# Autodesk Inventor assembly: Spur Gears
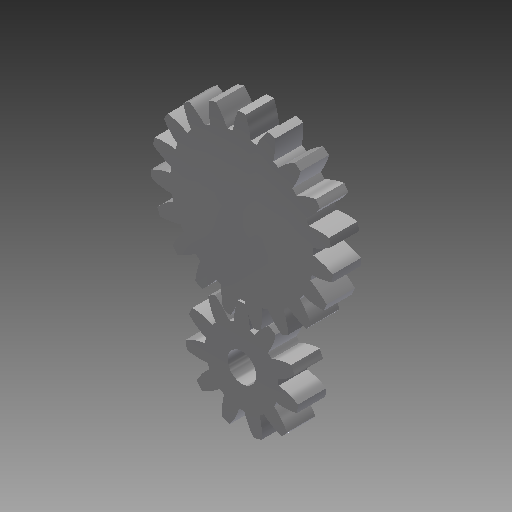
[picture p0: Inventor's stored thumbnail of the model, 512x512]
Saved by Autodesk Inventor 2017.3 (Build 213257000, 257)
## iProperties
ClientObjectVersion: 1
Created: 2020-03
Part Number: Spur Gears
Document SubType Name: Assembly
Designer: Tim_G
Categories: <?xml version="1.0" encoding="UTF-16"?> <MemberInstance><Categories><FamilyTemplate/><ParamToTemplateMap><ParamToTemplate><ParamToTemplate CategoryParameter="//
Author: Tim_G
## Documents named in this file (3)
- C:\Users\Tim_G\OneDrive - McMaster University\Documents\Documents\Books\McMaster First Year Courses\Winter Engineering 1C03\Project\Project Files (Prosthetic Frame Assembly)\Hand Assembly\Design Accelerator\Spur Gears5.iam
- C:\Users\Tim_G\OneDrive - McMaster University\Documents\Documents\Books\McMaster First Year Courses\Winter Engineering 1C03\Project\Project Files (Prosthetic Frame Assembly)\Hand Assembly\Design Accelerator\Spur Gear15.ipt
- C:\Users\Tim_G\OneDrive - McMaster University\Documents\Documents\Books\McMaster First Year Courses\Winter Engineering 1C03\Project\Project Files (Prosthetic Frame Assembly)\Hand Assembly\Design Accelerator\Spur Gear25.ipt
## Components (2 placed, 2 different names)
1. Spur Gear1:1 — Rotation:1
2. Spur Gear2:1 — Rotation:1
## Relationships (1: RelateRotation 1)
- Rotation:1 [RelateRotation]: Spur Gear1:1 ↔ Spur Gear2:1
